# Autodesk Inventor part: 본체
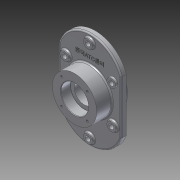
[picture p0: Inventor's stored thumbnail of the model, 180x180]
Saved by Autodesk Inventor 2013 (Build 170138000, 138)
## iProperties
Created: 2015-02
Part Number: 본체
Material: 알루미늄 6061
Document SubType Name: Modeling
Designer: kb
Density: 2.71 g/cm^3
Mass: 1636.71 g
Surface Area: 926.529 cm^2
Volume: 603.951 cm^3
Author: kb
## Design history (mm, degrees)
sketch "스케치1"
  geometry: L1 (-70, -60)-(70, -60); L2 (70, -60)-(70, 60); L3 (70, 60)-(-70, 60); L4 (-70, 60)-(-70, -60); L5 (-70, -60)-(70, 60); L6 (70, -60)-(-70, 60); A1 r 74 centre (0, 36) between (70, 60) and (-70, 60); A2 r 74 centre (0, -36) between (-70, -60) and (70, -60); 3 further points
  constraints: 12 end point, 6 point on circle, 2 centre point, 2 midpoint, 2 parallel, 1 horizontal, 1 perpendicular
  dimensions: "d0" = 120 distance of L1.end L2.end; "d2" = 140 distance of L2.end L3.end; "d3" = 50 distance from line of L3 point (0, 110); "d4" = 50 distance from line of point (0, -110) L1
extrude "돌출1" new body sketch "스케치1" distance "d5" = 12; taper "d6" = 0 deg
sketch "스케치2"
  geometry: L1 (60, 0)-(60, 0) reference; L2 (60, 0)-(60, 12) reference; L3 (60, 12)-(60, 12) reference; L4 (60, 0)-(60, 12) reference; L5 (-60, 0)-(-60, 0) reference; L6 (-60, 0)-(-60, 12) reference; L7 (-60, 12)-(-60, 12) reference; L8 (-60, 0)-(-60, 12) reference; L9 (-60, 12)-(60, 12) reference; L10 (-60, 0)-(60, 0) reference; L11 (110, 0)-(110, 12) reference; L12 (110, 12)-(60, 12) reference; L13 (-60, 12)-(-110, 12) reference; L14 (-110, 0)-(-110, 12) reference; L15 (0, 55.915)-(0, -38.906); L16 (50, 47)-(50, -23); L17 (31, 47)-(31, 25); L18 (0, 25)-(0, -1); L19 (31, -1)-(31, -23); L20 (31, 25)-(22.5, 25); L21 (22.5, 25)-(22.5, -1); L22 (22.5, -1)-(31, -1); L23 (50, 47)-(31, 47); L24 (50, -23)-(31, -23); L25 (-60, 0)-(60, 0) reference; L26 (60, 0)-(60, 12) reference; L27 (-60, 12)-(60, 12) reference; L28 (-60, 0)-(-60, 12) reference; 2 further points
  constraints: 20 end point, 3 parallel, 2 perpendicular, 1 midpoint, 1 point on line
  dimensions: "d7" = 70 distance of L16.start L16.end; "d10" = 100 diameter of L16 L15; "d11" = 22 distance of L17.start L17.end; "d12" = 22 distance of L19.start L19.end; "d13" = 62 diameter of L19 L15; "d14" = 62 diameter of L17 L15; "d62" = 45 diameter of L21 L15; "d63" = 23 distance between parallel lines of L24 L10
revolve "회전1" sketch "스케치2" stored, may be unused: angle "d16" = 90 deg
sketch "스케치3"
  geometry: L1 (70, -60)-(70, 60) reference; L2 (-70, 60)-(-70, -60) reference; L3 (53, 56.976)-(53, -56.976); L4 (-53, -56.976)-(-53, 56.976); L5 (-84.709, 0)-(99.231, 0); C1 r 10 at (0, 93); C2 r 10 at (0, -93); C3 r 10 at (-53, 42.5); C4 r 10 at (-53, -42.5); C5 r 10 at (53, 42.5); C6 r 10 at (53, -42.5); C7 r 50 at (0, 0) reference; A1 r 74 centre (0, -36) between (-70, -60) and (70, -60) reference; A2 r 74 centre (0, 36) between (70, 60) and (-70, 60) reference; A3 r 57 centre (0, 36) between (53, 56.976) and (-53, 56.976); A4 r 57 centre (0, -36) between (-53, -56.976) and (53, -56.976)
  constraints: 8 centre point, 6 end point, 6 point on circle, 5 equal radius, 5 point on line, 1 perpendicular, 5 other
  dimensions: "d17" = 17 distance between parallel lines of L2 L4; "d18" = 20 diameter of C1; "d89" = 85 distance of C4.centre C3.centre; "d90" = 85 distance of C6.centre C5.centre
extrude "돌출2" join sketch "스케치3" distance "d19" = 5; taper "d20" = 0 deg
sketch "스케치7"
  geometry: C1 r 10 at (0, 0) reference; C2 r 10 at (-53, -50.5) reference; C3 r 10 at (-53, -135.5) reference; C4 r 10 at (0, -186) reference; C5 r 10 at (53, -135.5) reference; C6 r 10 at (53, -50.5) reference; 1 further point
hole "구멍3" sketch "스케치7" at (0, 0), (53, -50.5), (53, -135.5), (0, -186), (-53, -135.5), (-53, -50.5) diameter "d47" = 11; stored, may be unused: countersink angle "d51" = 90 deg, drill point angle "d53" = 118 deg; dims "d48" = 10, "d49" = 4, "d50" = 2, "d52" = 13
fillet "모깎기1" dims "d54" = 0.3
fillet "모깎기2" dims "d55" = 3
chamfer "모따기1" distance "d56" = 1; stored, may be unused: second distance "d57" = 2, angle "d58" = 45 deg
sketch "스케치8"
  geometry: L1 (0, 154)-(0, -154) reference; L2 (-99.159, 0)-(99.159, 0) reference; 1 further point
  constraints: 1 point on line, 1 other
  dimensions: "d59" = 65 distance from line of L2 point (0, 65)
feature "엠보싱1" sketch "스케치8" dims "d0" = 120, "d2" = 140, "d3" = 50, "d4" = 50, "d60" = 1, "d61" = 0
sketch "스케치9"
  geometry: C1 r 22.5 at (0, 0) reference; C2 r 22.5 at (0, 0) reference; C3 r 22.5 at (0, 0)
  constraints: 1 centre point, 1 coincident
extrude "돌출3" cut sketch "스케치9" stored distance "d64" = 5; taper "d65" = 0 deg
sketch "스케치10" dims "d66" = 82
  geometry: L1 (0, 0)-(-28.991, 28.991); L2 (-84.24, 0)-(108.171, 0); L3 (0, 116.817)-(0, -134.614); C1 r 50 at (0, 0) reference; C2 r 50 at (0, 0) reference; C3 r 32 at (0, 0) reference; 3 further points
  constraints: 6 end point, 3 symmetric about line, 2 point on line, 1 coincident, 1 horizontal, 1 perpendicular, 3 other
  dimensions: "d69" = 45 deg angle of L2 L1
hole "구멍4" sketch "스케치10" at (-28.991, 28.991), (28.991, 28.991), (-28.991, -28.991), (28.991, -28.991) diameter "d71" = 4.917; stored, may be unused: countersink angle "d75" = 90 deg, drill point angle "d77" = 118 deg; dims "d72" = 10, "d73" = 4, "d74" = 2, "d76" = 13
sketch "스케치11" dims "d78" = 82
  geometry: L1 (-101.243, 0)-(126.277, 0); L2 (0, 135.665)-(0, -138.61); L3 (0, 0)-(-28.991, 28.991); C1 r 50 at (0, 0) reference; C2 r 50 at (0, 0) reference; C3 r 32 at (0, 0) reference; 3 further points
  constraints: 6 end point, 3 symmetric about line, 2 point on line, 1 coincident, 1 horizontal, 1 perpendicular, 3 other
  dimensions: "d80" = 45 deg angle of L1 L3
hole "구멍5" sketch "스케치11" at (-28.991, 28.991), (-28.991, -28.991), (28.991, -28.991), (28.991, 28.991) diameter "d82" = 4.917; stored, may be unused: countersink angle "d86" = 90 deg, drill point angle "d88" = 118 deg; dims "d83" = 10, "d84" = 4, "d85" = 2, "d87" = 13
node "솔리드1"
node "투영된 루프1"
node "투영된 루프2"
node "투영된 루프3"
node "투영된 루프4"
node "투영된 루프5"
node "투영된 루프6"
node "투영된 루프7"
node "투영된 루프8"
node "투영된 루프9"
node "투영된 루프10"
node "투영된 루프11"
